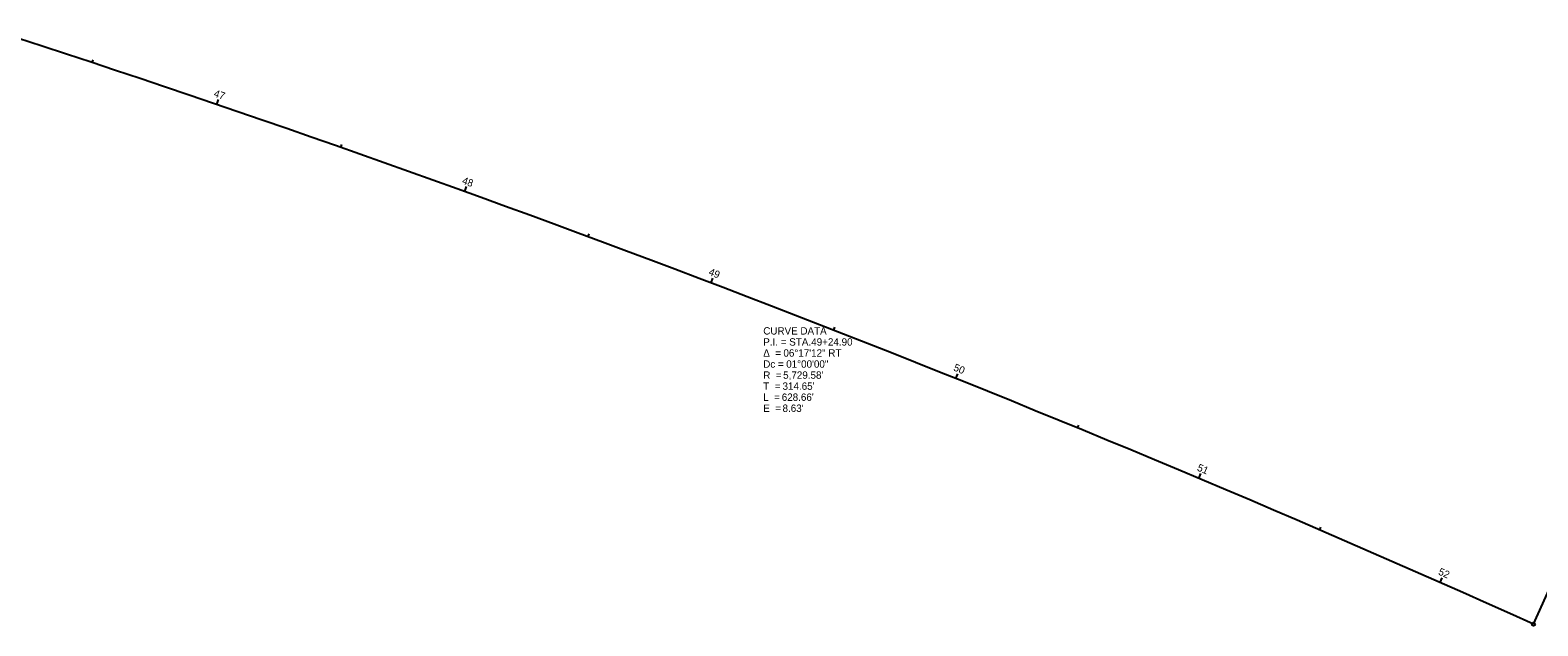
# Model space of a CAD drawing. Extents: x 2199669 to 2203518, y 635127 to 637305.
# Drawn here: x 2200451 to 2201024, y 635445 to 635671 of the extents above; entities that cross this region are included whole.
import ezdxf

# ---------------------------------------------------------------- set-up
doc = ezdxf.new("R2010")
doc.units = 0
for name, color, linetype in [('RD_P_GR_Lt', 7, 'Continuous'), ('RD_P_GR_Rt', 7, 'Continuous'), ('SC_Scratch1', 7, 'Continuous'), ('SC_Scratch2', 7, 'Continuous')]:
    doc.layers.add(name, color=color, linetype=linetype)

msp = doc.modelspace()

# ---------------------------------------------------------------- linework, layer by layer
at = {"layer": 'RD_P_GR_Lt'}
msp.add_line((2201022.7, 635445.4), (2201041.79, 635487.83), dxfattribs=at)
msp.add_circle((2201022.7, 635445.4), 0.6, dxfattribs=at)
at = {"layer": 'RD_P_GR_Rt'}
msp.add_arc((2198672.92, 630219.83), 5729.58, 65.787972, 72.074607, dxfattribs=at)
msp.add_arc((2198672.92, 630219.83), 5729.58, 65.787972, 72.074607, dxfattribs=at)
at = {"layer": 'SC_Scratch1'}
for p, q in [((2200474.14, 635658.91), (2200474.51, 635660.05)), ((2200521.53, 635642.99), (2200522.18, 635644.88)), ((2200568.79, 635626.65), (2200569.19, 635627.78)), ((2200615.9, 635609.9), (2200616.58, 635611.78)), ((2200662.86, 635592.74), (2200663.28, 635593.86)), ((2200709.67, 635575.17), (2200710.38, 635577.04)), ((2200756.33, 635557.19), (2200756.76, 635558.31)), ((2200802.83, 635538.81), (2200803.57, 635540.66)), ((2200849.16, 635520.02), (2200849.62, 635521.13)), ((2200895.33, 635500.82), (2200896.11, 635502.67)), ((2200941.33, 635481.23), (2200941.81, 635482.33)), ((2200987.16, 635461.23), (2200987.97, 635463.06))]:
    msp.add_line(p, q, dxfattribs=at)

# ---------------------------------------------------------------- texts
for s, rotation, p in [('47', 341.17711, (2200520.16, 635646.1)), ('48', 340.17711, (2200614.66, 635613)), ('49', 339.17711, (2200708.5, 635578.29)), ('50', 338.17711, (2200801.69, 635541.96)), ('51', 337.17711, (2200894.43, 635503.92)), ('52', 336.17711, (2200986.19, 635464.39))]:
    msp.add_text(s, height=2.8, rotation=rotation, dxfattribs=at).set_placement(p)
at = {"layer": 'SC_Scratch2'}
for s, p in [('CURVE DATA', (2200729.53, 635555.54)), ('Δ  = ', (2200729.53, 635547.14)), ('P.I. = STA. ', (2200729.53, 635551.34)), ('06°17\'12" RT', (2200737.21, 635547.14)), ('49+24.90', (2200747.8, 635551.34)), ('Dc = ', (2200729.53, 635542.94)), ('01°00\'00"', (2200738.27, 635542.94)), ('R  = ', (2200729.53, 635538.74)), ("5,729.58'", (2200737.11, 635538.74)), ('T  = ', (2200729.53, 635534.54)), ('L  = ', (2200729.53, 635530.34)), ("628.66'", (2200736.57, 635530.34)), ("314.65'", (2200736.87, 635534.54)), ('E  = ', (2200729.53, 635526.14)), ("8.63'", (2200736.87, 635526.14))]:
    msp.add_text(s, height=2.8, dxfattribs=at).set_placement(p)

doc.saveas('drawing.dxf')
